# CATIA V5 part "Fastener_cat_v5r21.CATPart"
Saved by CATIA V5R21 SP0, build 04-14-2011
Part number: Fastener
Bounding box of the stored display mesh (mm): x -5 to 5, y -5 to 5, z -48 to 0
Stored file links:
  D:\CATIA V5R21 E-RESOURCES\CATIA-V5R21\catia-v5r21-Tut\c14-catia-v5r21-tut\c14-catia-v5r21-tut02\Part & Asm files\Fastener_cat_v5r21.CATPart
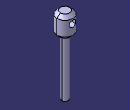
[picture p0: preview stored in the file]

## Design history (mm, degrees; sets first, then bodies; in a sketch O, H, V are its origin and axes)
Body1 (main body)
  Sketch1 on xy-plane, origin (0, 0, 0), H (1, 0, 0), V (0, 1, 0)
    circle A1 centre (0, 0) radius 5
    circle A2 centre (0, 0) radius 2
    radius A2 = 2
    radius A1 = 5
  MultiPad1: profile Sketch1, domains (length 0 / length 48; length 0 / length 13)
  Chamfer1: length 2, angle 45, on 2 edges
  Chamfer2: length 0.508, angle 45, on 1 edge
  Sketch2 on zx-plane, origin (-1.612, 0, 1.612), H (1, 0, 0), V (0, 0, -1)
    point P1 (1.612, 6.35)
    reference intersected line E1 through (1.612, 0) direction (0, 1) from yz-plane
    distance P1 H = 6.35
    coincidence: E1 P1
  Hole1: placed by Sketch2, at (0, 0, -4.738) direction (0, -1, 0), diameter 4, depth 10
